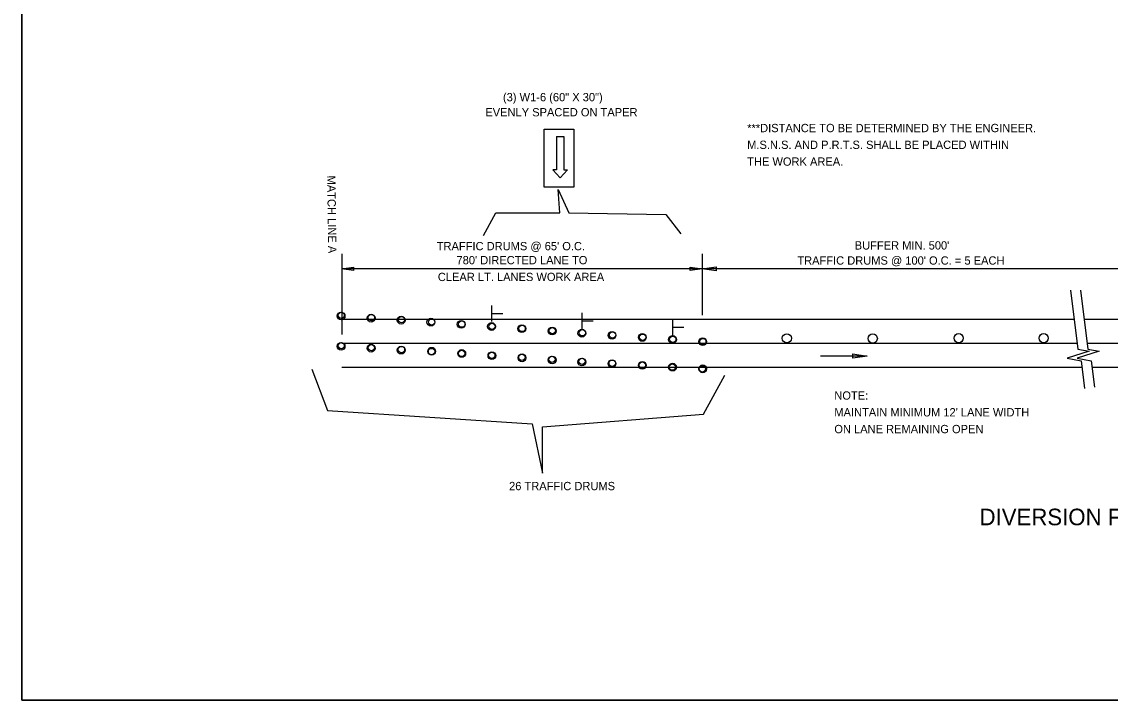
# Model space of a CAD drawing. Extents: x 1374027 to 1374537, y 380415 to 381405.
# Drawn here: x 1374027.1 to 1374105.8, y 380855.2 to 380904.2 of the extents above; entities that cross this region are included whole.
import ezdxf

# ---------------------------------------------------------------- set-up
doc = ezdxf.new("R2010")
doc.units = 0
doc.layers.add('Default', color=7, linetype='Continuous')
doc.layers.add('DSN_DRFT_Junk-No-Plot', color=7, linetype='Continuous')

msp = doc.modelspace()

# ---------------------------------------------------------------- linework, layer by layer
at = {"layer": 'Default'}
for p, q in [((1374065.768, 380895.927), (1374065.768, 380893.537)), ((1374065.768, 380895.927), (1374066.3, 380895.927)), ((1374066.3, 380895.927), (1374066.3, 380893.537)), ((1374065.768, 380893.537), (1374065.501, 380893.537)), ((1374065.501, 380893.537), (1374066.034, 380892.953)), ((1374066.034, 380892.953), (1374066.566, 380893.537)), ((1374066.3, 380893.537), (1374066.566, 380893.537)), ((1374050.247, 380887.446), (1374050.247, 380881.618)), ((1374076.305, 380887.446), (1374076.305, 380883.018)), ((1374050.228, 380886.368), (1374051.097, 380886.498)), ((1374051.097, 380886.498), (1374051.097, 380886.237)), ((1374075.436, 380886.237), (1374075.436, 380886.498)), ((1374075.436, 380886.498), (1374076.305, 380886.368)), ((1374076.305, 380886.368), (1374077.336, 380886.522)), ((1374077.336, 380886.522), (1374077.336, 380886.213)), ((1374076.305, 380886.368), (1374050.228, 380886.368)), ((1374051.097, 380886.237), (1374050.228, 380886.368)), ((1374050.247, 380885.923), (1374050.247, 380881.618)), ((1374076.305, 380886.368), (1374075.436, 380886.237)), ((1374107.216, 380886.368), (1374076.305, 380886.368)), ((1374077.336, 380886.213), (1374076.305, 380886.368)), ((1374061.087, 380882.56), (1374061.087, 380883.721)), ((1374050.247, 380882.73), (1374077.152, 380882.73)), ((1374061.104, 380883.138), (1374061.897, 380883.138)), ((1374067.628, 380882.018), (1374067.628, 380883.18)), ((1374067.645, 380882.596), (1374068.438, 380882.596)), ((1374074.185, 380881.567), (1374074.185, 380882.728)), ((1374076.324, 380882.73), (1374103.218, 380882.73)), ((1374103.946, 380882.73), (1374107.216, 380882.73)), ((1374074.202, 380882.145), (1374074.994, 380882.145)), ((1374050.247, 380880.992), (1374077.528, 380880.992)), ((1374076.235, 380880.992), (1374103.435, 380880.992)), ((1374104.164, 380880.992), (1374107.146, 380880.992)), ((1374087.224, 380879.904), (1374087.224, 380880.213)), ((1374087.224, 380880.213), (1374088.254, 380880.059)), ((1374088.254, 380880.059), (1374084.875, 380880.059)), ((1374088.254, 380880.059), (1374087.224, 380879.904)), ((1374050.247, 380879.253), (1374077.871, 380879.253)), ((1374076.283, 380879.253), (1374103.79, 380879.253)), ((1374104.518, 380879.253), (1374107.194, 380879.253))]:
    msp.add_line(p, q, dxfattribs=at)
msp.add_lwpolyline([(1374064.892, 380892.27), (1374064.892, 380896.462), (1374067.035, 380896.462), (1374067.035, 380892.27)], close=True, dxfattribs=at)
for points in [[(1374060.482, 380888.785), (1374061.383, 380890.415), (1374066.006, 380890.415), (1374065.886, 380892.103), (1374066.667, 380890.415), (1374073.691, 380890.298), (1374074.772, 380888.901)], [(1374102.956, 380884.824), (1374103.491, 380880.549), (1374104.316, 380880.403), (1374102.714, 380879.917), (1374103.733, 380879.723), (1374103.975, 380877.716)], [(1374103.685, 380884.824), (1374104.219, 380880.549), (1374105.045, 380880.403), (1374103.442, 380879.917), (1374104.462, 380879.723), (1374104.693, 380877.802)], [(1374048.067, 380879.108), (1374049.194, 380876.117), (1374064.004, 380875.169), (1374064.756, 380871.594), (1374064.756, 380874.95), (1374076.405, 380875.853), (1374077.959, 380878.687)]]:
    msp.add_lwpolyline(points, dxfattribs=at)
for centre, radius in [((1374050.188, 380882.956), 0.281), ((1374050.188, 380883.001), 0.229), ((1374050.201, 380883), 0.229), ((1374052.362, 380882.803), 0.281), ((1374052.381, 380882.843), 0.229), ((1374054.535, 380882.651), 0.281), ((1374054.562, 380882.685), 0.229), ((1374056.683, 380882.514), 0.281), ((1374056.743, 380882.528), 0.229), ((1374058.877, 380882.355), 0.281), ((1374058.923, 380882.37), 0.229), ((1374061.071, 380882.196), 0.281), ((1374061.104, 380882.213), 0.229), ((1374063.265, 380882.036), 0.281), ((1374063.285, 380882.055), 0.229), ((1374065.459, 380881.877), 0.281), ((1374065.465, 380881.897), 0.229), ((1374067.607, 380881.712), 0.281), ((1374067.646, 380881.74), 0.229), ((1374069.794, 380881.559), 0.281), ((1374069.827, 380881.582), 0.229), ((1374050.188, 380880.767), 0.281), ((1374050.188, 380880.812), 0.229), ((1374050.201, 380880.811), 0.229), ((1374071.981, 380881.407), 0.281), ((1374072.007, 380881.425), 0.229), ((1374074.168, 380881.255), 0.281), ((1374074.188, 380881.267), 0.229), ((1374076.355, 380881.102), 0.281), ((1374076.356, 380881.111), 0.229), ((1374076.369, 380881.11), 0.229), ((1374082.441, 380881.345), 0.333), ((1374088.655, 380881.33), 0.333), ((1374094.868, 380881.351), 0.333), ((1374101.017, 380881.352), 0.333), ((1374052.362, 380880.628), 0.281), ((1374052.379, 380880.67), 0.229), ((1374054.535, 380880.49), 0.281), ((1374054.556, 380880.529), 0.229), ((1374056.738, 380880.409), 0.281), ((1374056.734, 380880.388), 0.229), ((1374058.918, 380880.249), 0.281), ((1374058.912, 380880.247), 0.229), ((1374061.098, 380880.09), 0.281), ((1374061.09, 380880.106), 0.229), ((1374063.278, 380879.931), 0.281), ((1374063.268, 380879.965), 0.229), ((1374065.459, 380879.771), 0.281), ((1374065.445, 380879.824), 0.229), ((1374067.607, 380879.634), 0.281), ((1374067.623, 380879.683), 0.229), ((1374069.794, 380879.509), 0.281), ((1374069.801, 380879.542), 0.229), ((1374071.981, 380879.385), 0.281), ((1374071.979, 380879.401), 0.229), ((1374074.168, 380879.26), 0.281), ((1374074.157, 380879.26), 0.229), ((1374076.355, 380879.135), 0.281), ((1374076.322, 380879.12), 0.229), ((1374076.335, 380879.119), 0.229)]:
    msp.add_circle(centre, radius, dxfattribs=at)
at = {"layer": 'DSN_DRFT_Junk-No-Plot'}
for points in [[(1374027.083, 380965.174), (1374197.083, 380965.174), (1374197.083, 380855.174), (1374027.083, 380855.174)], [(1374027.083, 380965.174), (1374027.083, 380855.174), (1374197.083, 380855.174), (1374197.083, 380965.174)]]:
    msp.add_lwpolyline(points, close=True, dxfattribs=at)

# ---------------------------------------------------------------- texts
at = {"layer": 'Default'}
for s, rotation, p in [('(3) W1-6 (60" X 30")', 0.00754, (1374061.902, 380898.482)), ('EVENLY SPACED ON TAPER', 0.00754, (1374060.624, 380897.39)), ('MATCH LINE A', 270.80593, (1374049.178, 380893.107))]:
    msp.add_text(s, height=0.6, rotation=rotation, dxfattribs=at).set_placement(p)
for s, height, p in [('***DISTANCE TO BE DETERMINED BY THE ENGINEER.', 0.6, (1374079.569, 380896.248)), ('M.S.N.S. AND P.R.T.S. SHALL BE PLACED WITHIN', 0.6, (1374079.569, 380895.035)), ('THE WORK AREA.', 0.6, (1374079.569, 380893.822)), ("TRAFFIC DRUMS @ 65' O.C.", 0.6, (1374057.108, 380887.709)), ("BUFFER MIN. 500'", 0.6, (1374087.352, 380887.761)), ("780' DIRECTED LANE TO", 0.6, (1374058.538, 380886.695)), ("TRAFFIC DRUMS @ 100' O.C. = 5 EACH", 0.6, (1374083.198, 380886.669)), ('CLEAR LT. LANES WORK AREA', 0.6, (1374057.187, 380885.482)), ('NOTE:', 0.6, (1374085.874, 380876.907)), ("MAINTAIN MINIMUM 12' LANE WIDTH", 0.6, (1374085.874, 380875.694)), ('ON LANE REMAINING OPEN', 0.6, (1374085.874, 380874.481)), ('26 TRAFFIC DRUMS', 0.6, (1374062.342, 380870.36)), ('DIVERSION FOR LT. LANE WORK ZONE', 1.2, (1374096.385, 380867.824))]:
    msp.add_text(s, height=height, dxfattribs=at).set_placement(p)

doc.saveas('drawing.dxf')
